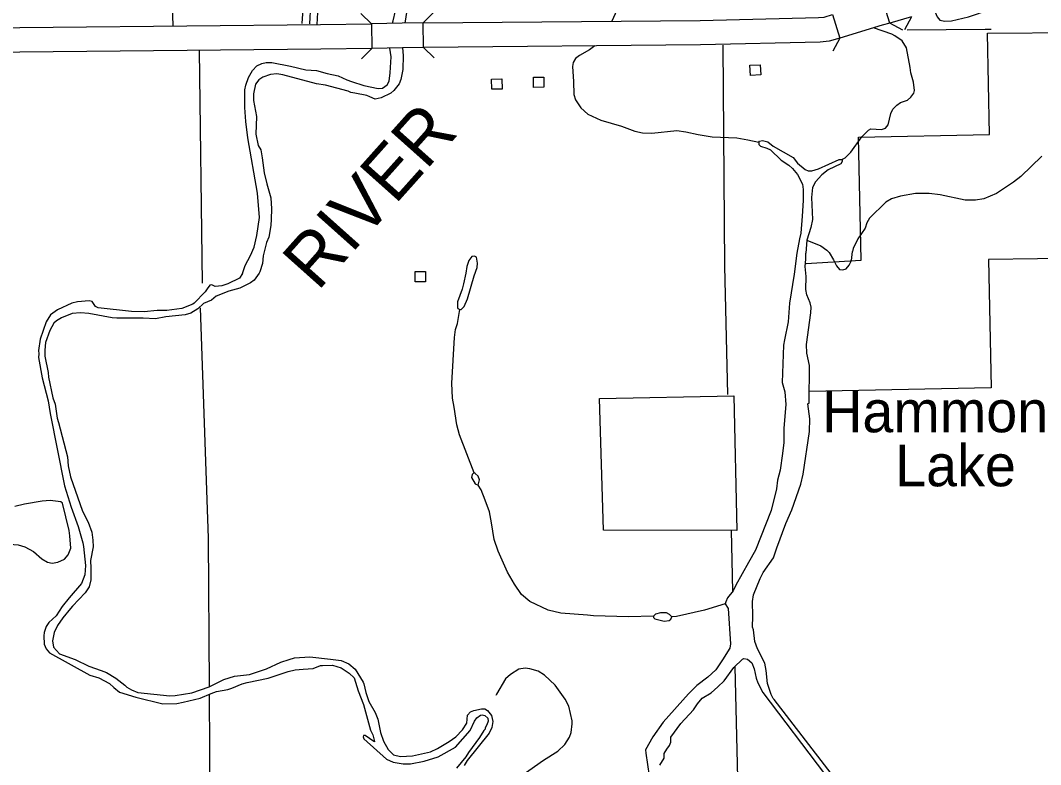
# Model space of a CAD drawing. Extents: x 1084508 to 1142749, y 1057638 to 1093403.
# Drawn here: x 1086974 to 1090220, y 1085312 to 1087680 of the extents above; entities that cross this region are included whole.
import ezdxf

# ---------------------------------------------------------------- set-up
doc = ezdxf.new("R2010")
doc.units = 0
for name, color, linetype in [('Level 10', 7, 'Continuous'), ('Level 32', 7, 'Continuous'), ('Level 35', 7, 'Continuous'), ('Level 37', 7, 'Continuous'), ('Level 4', 7, 'Continuous'), ('Level 5', 7, 'Continuous'), ('Level 56', 7, 'Continuous'), ('Level 7', 7, 'Continuous'), ('Level 9', 7, 'Continuous')]:
    doc.layers.add(name, color=color, linetype=linetype)

msp = doc.modelspace()

# ---------------------------------------------------------------- linework, layer by layer
at = {"layer": 'Level 10'}
for points in [[(1089740.3, 1087671.9), (1089717.5, 1087747)], [(1088255.8, 1087672.1), (1089137.3, 1087680.5), (1089513.8, 1087689.3), (1089532, 1087691.1), (1089558.6, 1087699.2)], [(1089558.6, 1087699.2), (1089581.5, 1087624.1)], [(1085801.9, 1087646.2), (1087928.8, 1087666.8), (1088091.3, 1087669.7)], [(1088255.8, 1087672.1), (1088189.3, 1087671.5), (1088091.3, 1087669.7)], [(1088091.3, 1087669.7), (1088092.5, 1087591.3)], [(1088257, 1087593.7), (1088255.8, 1087672.1)], [(1089740.3, 1087671.9), (1089716.4, 1087665.2), (1089581.5, 1087624.1)], [(1089809.9, 1087691.2), (1089740.3, 1087671.9)], [(1089581.5, 1087624.1), (1089547.4, 1087613.7), (1089518.5, 1087610.9), (1089138.6, 1087602.1), (1088257, 1087593.7)], [(1088092.5, 1087591.3), (1087929.9, 1087588.3), (1085800.4, 1087567.7)], [(1088257, 1087593.7), (1088190.4, 1087593), (1088092.5, 1087591.3)]]:
    msp.add_lwpolyline(points, dxfattribs=at)
at = {"layer": 'Level 32'}
for points in [[(1087886, 1087783.3), (1087874, 1087731.9), (1087870.2, 1087670.7)], [(1087908.9, 1087778), (1087897.4, 1087728.5), (1087893.7, 1087669.2)], [(1087931.9, 1087772.6), (1087920.8, 1087725), (1087917.2, 1087667.7)]]:
    msp.add_lwpolyline(points, dxfattribs=at)
at = {"layer": 'Level 35'}
for points in [[(1088858.8, 1087842.5), (1088838.1, 1087829.8), (1088818.6, 1087822.8), (1088794.4, 1087820.6), (1088699.8, 1087825.2), (1088627.7, 1087833.6), (1088569.4, 1087843.3), (1088529.9, 1087855.4), (1088502.3, 1087861.5), (1088475.4, 1087862.5), (1088454.7, 1087860.8), (1088410.3, 1087852.2), (1088343.8, 1087829.2), (1088293.6, 1087807.5), (1088265.3, 1087790.1), (1088244.4, 1087775.4), (1088229, 1087757.5), (1088210.3, 1087726.3), (1088203.6, 1087711.5), (1088197, 1087671.6)], [(1088858.8, 1087842.5), (1088876.8, 1087821.1), (1088886.7, 1087802.9), (1088909, 1087788), (1088916.4, 1087775.1), (1088916.8, 1087763.7), (1088909.1, 1087749.9), (1088872.1, 1087713.2), (1088855.6, 1087677.9)], [(1089883, 1087711.5), (1089891.2, 1087691.8), (1089899.5, 1087680.8), (1089915.6, 1087677.9), (1089936.3, 1087679.4), (1089990.7, 1087691.8), (1090056.2, 1087714.4)], [(1089762.7, 1087410.8), (1089774.1, 1087419.1), (1089796.8, 1087426.5), (1089807.5, 1087435.5), (1089817.1, 1087448.4), (1089819.3, 1087457.7), (1089815.8, 1087483.7), (1089807.7, 1087513.3), (1089805.7, 1087530.9), (1089793.1, 1087593.4), (1089779.3, 1087614.9), (1089756.4, 1087631.7), (1089747.4, 1087636.4), (1089688.8, 1087656.8)], [(1088802.4, 1087598.9), (1088784.8, 1087587.1), (1088752.7, 1087568.3), (1088739.9, 1087559), (1088732.8, 1087546.1), (1088731, 1087533.5), (1088733.7, 1087486.3), (1088735, 1087444.6), (1088740.1, 1087427.5), (1088757, 1087402.1)], [(1088190.4, 1087593.1), (1088192.6, 1087568.1), (1088191.1, 1087524.3), (1088184.9, 1087492.5)], [(1088184.9, 1087492.5), (1088178.9, 1087478.8), (1088162.7, 1087457.4), (1088152.9, 1087448.5), (1088122.3, 1087433.8), (1088102.5, 1087429.9), (1088085.6, 1087437.2), (1088076, 1087441.8), (1088038.6, 1087448.3), (1088026, 1087450.4), (1088017, 1087455.1), (1087944.5, 1087473.8), (1087916, 1087478.7), (1087809.4, 1087507.2), (1087789.8, 1087509.9), (1087770, 1087507.9), (1087745.1, 1087500), (1087732.9, 1087491.1), (1087722.4, 1087477.4), (1087716, 1087446.3), (1087715.8, 1087424.9), (1087725.5, 1087374.9), (1087722.9, 1087318.1), (1087731.2, 1087282.5), (1087738.9, 1087268.3), (1087743.9, 1087243.3)], [(1089352.1, 1087294), (1089369.2, 1087280.5), (1089432.8, 1087243.7), (1089447.2, 1087225.8), (1089471.5, 1087206.2), (1089480.3, 1087201.1), (1089492.2, 1087201), (1089514, 1087207.5), (1089579.1, 1087238), (1089587.5, 1087237.1), (1089598.6, 1087242.8), (1089616.2, 1087261.1), (1089651.5, 1087310), (1089672.5, 1087331.2), (1089680.2, 1087335.3), (1089714.3, 1087333.4), (1089727.2, 1087337.7), (1089735.2, 1087347.4), (1089743.2, 1087384), (1089749.7, 1087397.4), (1089762.7, 1087410.8)], [(1088757, 1087402.1), (1088779.2, 1087381.5), (1088820.8, 1087363), (1088886.7, 1087343.7), (1088929.2, 1087327.6), (1088953.3, 1087322.6), (1088982.9, 1087321.5), (1089062.4, 1087329.7), (1089091.1, 1087325.8), (1089131.1, 1087317.2), (1089174.8, 1087309.7)], [(1089174.8, 1087309.7), (1089254, 1087306.1), (1089288.3, 1087300)], [(1089288.3, 1087300), (1089323.8, 1087293), (1089326.2, 1087296.2), (1089335.2, 1087297.8), (1089352.1, 1087294)], [(1089323.8, 1087293), (1089323.7, 1087285.1), (1089328.9, 1087280.2), (1089349, 1087274.1), (1089361.2, 1087268.5)], [(1087743.9, 1087243.3), (1087750.1, 1087195), (1087758.1, 1087160), (1087770.7, 1087115.8), (1087773.6, 1087080.3), (1087772, 1087047.8), (1087771.5, 1087027.6), (1087764.7, 1086990.2), (1087757.7, 1086972.9), (1087747, 1086930.6), (1087744.1, 1086906.9), (1087735.7, 1086879.8), (1087733.6, 1086875.6)], [(1089361.3, 1087268.5), (1089394.5, 1087235.4), (1089419.1, 1087219.4), (1089430.4, 1087209.4), (1089446.3, 1087189.8), (1089462.3, 1087159.2), (1089464.7, 1087142.3), (1089464.8, 1087106.7), (1089461.6, 1087057.2), (1089457.3, 1087002.8), (1089453, 1086984.7), (1089444.6, 1086939)], [(1090223.8, 1087248.5), (1090157.5, 1087184), (1090133.6, 1087165.8), (1090080.2, 1087129.8), (1090039.9, 1087112.2), (1090013, 1087107.7), (1089980.2, 1087108.4), (1089900.2, 1087124.9), (1089865.4, 1087129.6), (1089822.6, 1087129.6), (1089774.7, 1087120.8), (1089746.1, 1087112.8), (1089728.2, 1087102.1), (1089676.3, 1087051), (1089667.7, 1087035.9), (1089662, 1087019), (1089639, 1086985.4), (1089624.1, 1086953.9), (1089621.9, 1086945)], [(1089588.4, 1087236.7), (1089589, 1087231.4), (1089584.5, 1087223.3), (1089544.3, 1087204.5), (1089524.1, 1087189), (1089503.5, 1087166.8), (1089494.4, 1087148.2), (1089491.5, 1087116.9), (1089494.4, 1087046.1), (1089489, 1087021.6), (1089476.4, 1086980.9), (1089520.5, 1086962.7), (1089540.2, 1086949.5), (1089547.4, 1086941.6)], [(1089476.4, 1086980.9), (1089472.9, 1086939.5)], [(1088417.5, 1086240.1), (1088371.2, 1086360.8), (1088362.5, 1086393.5), (1088354, 1086449.6), (1088348.9, 1086478.1), (1088346.7, 1086526), (1088355, 1086671.2), (1088358.2, 1086696.9), (1088364.6, 1086716.1), (1088372, 1086760.6), (1088376.5, 1086759.9), (1088386.1, 1086769.8), (1088396.3, 1086794.3), (1088417.8, 1086867.8), (1088427.1, 1086893.5), (1088428.9, 1086907.5), (1088425.2, 1086926.6), (1088419.1, 1086930.1), (1088411, 1086928.7), (1088400.6, 1086916), (1088394.8, 1086897.4), (1088391, 1086875.8), (1088384.4, 1086841.4), (1088380.1, 1086824.8), (1088365, 1086784.6), (1088365.1, 1086766.3), (1088366.2, 1086763.2), (1088369.8, 1086761.2)], [(1089444.6, 1086939), (1089436.1, 1086872.6), (1089421.7, 1086780.1), (1089417.5, 1086720.9), (1089405.9, 1086663.5), (1089402.2, 1086646.6), (1089398.2, 1086527.8), (1089406.1, 1086498.2), (1089409.5, 1086457.3), (1089402.8, 1086382.5), (1089403, 1086337.1), (1089398.9, 1086302.2), (1089391.2, 1086249.2), (1089383.6, 1086217.2), (1089379.8, 1086189.3), (1089362.5, 1086120), (1089312.8, 1085993.7), (1089291, 1085954.9), (1089250.5, 1085882.3), (1089242.2, 1085864.9), (1089224.3, 1085842.6), (1089218.6, 1085830)], [(1089475.5, 1086649.1), (1089489.1, 1086750), (1089490.2, 1086767.4), (1089487.1, 1086781.5), (1089476.5, 1086806.9), (1089473.5, 1086824.1), (1089474.5, 1086865.2), (1089471.5, 1086897.5), (1089473.6, 1086920.7), (1089472.9, 1086939.5)], [(1089547.4, 1086941.6), (1089561.8, 1086918.4), (1089570.8, 1086899.6), (1089580.1, 1086888), (1089590.6, 1086886), (1089601.1, 1086889.9), (1089611.3, 1086900.8), (1089618.2, 1086916), (1089621.9, 1086945)], [(1089372.9, 1085519), (1089369.6, 1085522), (1089363.4, 1085535.3), (1089350.8, 1085569.8), (1089347, 1085611.6), (1089342.8, 1085635), (1089319.4, 1085679.7), (1089310.5, 1085703.3), (1089306.3, 1085740.3), (1089304, 1085749.4), (1089304.6, 1085784.4), (1089303.8, 1085831.1), (1089307.2, 1085852.4), (1089327.5, 1085904.2), (1089337.1, 1085922.6), (1089370.5, 1085970.2), (1089380.7, 1086001.6), (1089409.9, 1086079.3), (1089428.4, 1086122.7), (1089457.2, 1086203.9), (1089464.5, 1086235.8), (1089484.5, 1086372.1), (1089485.8, 1086412.2), (1089479.6, 1086459.6), (1089483.5, 1086462.9), (1089484.8, 1086581.6), (1089476.4, 1086621), (1089475.5, 1086649.1)], [(1088416.9, 1086240.1), (1088411.8, 1086234.5), (1088409.7, 1086225.6), (1088420.7, 1086205.6), (1088430.3, 1086201.3)], [(1089216.3, 1085823.3), (1089151.2, 1085803), (1089061.8, 1085783.4), (1089046.7, 1085781.8), (1089039.2, 1085789.6), (1089029.5, 1085794.5), (1089010.6, 1085794.9), (1088995.4, 1085790.5), (1088988.1, 1085784.4), (1088908.9, 1085782.1), (1088797.7, 1085785.2), (1088778.7, 1085787.8), (1088693.8, 1085794), (1088653.1, 1085802.8), (1088595.6, 1085830.5), (1088569.1, 1085852.6), (1088546.2, 1085885.7), (1088523.7, 1085924.1), (1088493.9, 1085990.6), (1088481.5, 1086028.5), (1088473.2, 1086081.4), (1088466.6, 1086115.9), (1088453.2, 1086153.7), (1088440.4, 1086186.3), (1088430.3, 1086201.3), (1088435.2, 1086217.6), (1088431.2, 1086230), (1088420.8, 1086238.4), (1088417.5, 1086240.1)], [(1087131.6, 1086039.5), (1087128.9, 1086056.7), (1087108, 1086144.1), (1087102.7, 1086148), (1087068.6, 1086151.8), (1087043.8, 1086150.6), (1086987.6, 1086140.2), (1086956.8, 1086133.4)], [(1086512.6, 1085950.2), (1086540.2, 1085917.7), (1086543.8, 1085915.3), (1086552.5, 1085917.6), (1086641.6, 1085951), (1086653.7, 1085953.8), (1086758.3, 1085986.7), (1086810.8, 1086001.7), (1086864.9, 1086014.3), (1086894.1, 1086016), (1086911.7, 1086015.8), (1086967.6, 1086011.1), (1086988.4, 1086005.1), (1087015.8, 1085990), (1087042.7, 1085966.3), (1087060.1, 1085955.7), (1087075.7, 1085952.6), (1087093.8, 1085956.3), (1087114.4, 1085965.5), (1087126.1, 1085978.9), (1087134.9, 1086000.2), (1087131.6, 1086039.5)], [(1089218.6, 1085830), (1089216.3, 1085823.3), (1089226.1, 1085808.9), (1089233.8, 1085695.7), (1089231.2, 1085682.6), (1089208, 1085645), (1089187.4, 1085613.4), (1089161.1, 1085589.8), (1089126.4, 1085563.9), (1089100.3, 1085536.8), (1089019.4, 1085446.6), (1088986, 1085399.7), (1088963.3, 1085358.5), (1088963.8, 1085348.2), (1088975.2, 1085275.5)], [(1088988.1, 1085784.4), (1088988.6, 1085779.7), (1088992.6, 1085776.1), (1089022.2, 1085768.3), (1089038.5, 1085770.3), (1089043.6, 1085774.4), (1089046.7, 1085781.8)], [(1089039.1, 1085372.8), (1089043.7, 1085383.4), (1089044.2, 1085398.6), (1089075.6, 1085442.6), (1089115.5, 1085485.8), (1089128.4, 1085505.3), (1089143.4, 1085522.7), (1089171.9, 1085540.1), (1089193.4, 1085558.8), (1089213.3, 1085578.3), (1089244.1, 1085620.4), (1089272.1, 1085646.9), (1089276.4, 1085649), (1089287.8, 1085647.4), (1089301.9, 1085635.1), (1089309.1, 1085616.8), (1089314.8, 1085586.7), (1089320.5, 1085571.9), (1089336.7, 1085540.7), (1089533.1, 1085282.1), (1089568.2, 1085230.9)], [(1088516.2, 1085239.6), (1088639.1, 1085326), (1088684.7, 1085354.9), (1088706.4, 1085375.8), (1088721.4, 1085398.6), (1088726.4, 1085413.3), (1088729.6, 1085440.9), (1088729.7, 1085451), (1088718.8, 1085497.9), (1088707.1, 1085520), (1088675.2, 1085564.3), (1088642, 1085596), (1088621.6, 1085609.2), (1088595.4, 1085616.9), (1088580.6, 1085618.1), (1088560.6, 1085615.3), (1088533.3, 1085598.9), (1088517.3, 1085584.2), (1088489.3, 1085536.2), (1088487, 1085531.1)], [(1089582.2, 1085245.9), (1089372.9, 1085519)], [(1089008.3, 1085310.1), (1089022.1, 1085331.9), (1089022.7, 1085346.8), (1089030.5, 1085360.7), (1089039.1, 1085372.8)]]:
    msp.add_lwpolyline(points, dxfattribs=at)
at = {"layer": 'Level 37'}
for points in [[(1088057.5, 1087702.5), (1088091.3, 1087669.7)], [(1088255.8, 1087672.1), (1088288.5, 1087705.9)], [(1089781.9, 1087649.7), (1089740.3, 1087671.9)], [(1089809.9, 1087691.2), (1089786.7, 1087650.2)], [(1089581.5, 1087624.1), (1089559.3, 1087582.6)], [(1088092.5, 1087591.3), (1088059.8, 1087557.5)], [(1088290.8, 1087560.9), (1088257, 1087593.7)]]:
    msp.add_lwpolyline(points, dxfattribs=at)
at = {"layer": 'Level 4'}
msp.add_lwpolyline([(1090063.3, 1087651.6), (1090043.8, 1087651.3), (1089795.6, 1087649.1)], dxfattribs=at)
at = {"layer": 'Level 5'}
msp.add_line((1087543.3, 1087584.6), (1087552.4, 1086843.6), dxfattribs=at)
for points in [[(1087372.3, 1090942.1), (1087391.7, 1090120.4), (1087410.2, 1089282), (1087459.1, 1087662.2)], [(1089209.3, 1087601.3), (1089214.1, 1086898.4), (1089223.9, 1086489.4)], [(1087545.9, 1086765.7), (1087571.4, 1086031.9), (1087574.3, 1085558.7)], [(1089235.9, 1086056.4), (1089239.4, 1085913), (1089240.4, 1085861.2)], [(1089247.1, 1085623.3), (1089256.6, 1085224.9), (1089261.8, 1084966.8)], [(1087574.5, 1085535.1), (1087576.6, 1085186.7), (1087591.7, 1084372)]]:
    msp.add_lwpolyline(points, dxfattribs=at)
at = {"layer": 'Level 56'}
for points in [[(1089296.8, 1087505.4), (1089295.6, 1087538), (1089328.4, 1087539.3), (1089329.6, 1087506.6)], [(1088474.1, 1087461), (1088473.6, 1087493.7), (1088506.4, 1087494.1), (1088506.8, 1087461.5)], [(1088607.3, 1087466.6), (1088606.6, 1087499.2), (1088639.3, 1087499.9), (1088640, 1087467.3)], [(1088230.1, 1086848.2), (1088230.1, 1086880.9), (1088262.8, 1086880.9), (1088262.8, 1086848.2)]]:
    msp.add_lwpolyline(points, close=True, dxfattribs=at)
at = {"layer": 'Level 7'}
for points in [[(1089473, 1086904.1), (1089473, 1086906.3), (1089649, 1086917), (1089641.2, 1087308.4), (1090057.9, 1087316.8), (1090051.4, 1087640.2), (1090337.1, 1087641.8)], [(1090867.8, 1087146.3), (1090674.1, 1087142.4), (1090678.3, 1086928.3), (1090054.3, 1086919.8), (1090062.5, 1086510.4), (1089483.9, 1086498.9)]]:
    msp.add_lwpolyline(points, dxfattribs=at)
msp.add_lwpolyline([(1089244, 1086485.9), (1089253.7, 1086056.7), (1088829.8, 1086057.3), (1088816.3, 1086477)], close=True, dxfattribs=at)
at = {"layer": 'Level 9'}
for points in [[(1088158.5, 1087671), (1088159.8, 1087679), (1088168.1, 1087710.8), (1088198.1, 1087766.8), (1088220.4, 1087794.7), (1088257, 1087826.6), (1088282.8, 1087843.6), (1088312.5, 1087858), (1088334.3, 1087863.8), (1088370.7, 1087884.7), (1088386.2, 1087892.6), (1088522.9, 1087901.8), (1088545.9, 1087898.8), (1088572.7, 1087889.8), (1088624.8, 1087877.2)], [(1088027.2, 1087485.4), (1088067.3, 1087473.3), (1088112.4, 1087463.4), (1088125.9, 1087465.1), (1088141.3, 1087474.9), (1088147.1, 1087487), (1088151.2, 1087513), (1088153.7, 1087564.1), (1088149.9, 1087592.3)], [(1087680.8, 1086874.9), (1087689.9, 1086900.4), (1087706.4, 1086931.6), (1087717.7, 1086958.2), (1087726.7, 1086995.4), (1087734.6, 1087052.7), (1087728.9, 1087129.9), (1087697.5, 1087306.4), (1087691.2, 1087358.5), (1087688.3, 1087403.1), (1087688.1, 1087459.8), (1087691.3, 1087474.4), (1087700.2, 1087498.7), (1087712.5, 1087521.2), (1087726.8, 1087535.6), (1087742.4, 1087543.6), (1087756, 1087546.7), (1087774, 1087546.1), (1087833.3, 1087535.1), (1087882.5, 1087523.1), (1087916.3, 1087520.9), (1087950, 1087510.8), (1087985.6, 1087504), (1088012.5, 1087490.8), (1088027.2, 1087485.4)], [(1087680.8, 1086874.9), (1087671.2, 1086860.1), (1087634, 1086841.7), (1087615.4, 1086835.1), (1087594.4, 1086833.2), (1087582.8, 1086838.7), (1087576.9, 1086837.5), (1087568, 1086826), (1087561.8, 1086816.3), (1087526.6, 1086780.6), (1087522.7, 1086777.5), (1087487.5, 1086763), (1087440.2, 1086756.7), (1087409.4, 1086757.2), (1087367.7, 1086753.1), (1087327.7, 1086754.1), (1087221.2, 1086765), (1087212.8, 1086769.6), (1087203, 1086785.3), (1087193.1, 1086787.7), (1087156.1, 1086785), (1087137.7, 1086780.7), (1087092.4, 1086759.4), (1087069.9, 1086742.9), (1087056.1, 1086721.4), (1087036.9, 1086665.3), (1087032.2, 1086630.1), (1087032.4, 1086618.7)], [(1087733.6, 1086875.6), (1087718.1, 1086853.1), (1087706.5, 1086844.7), (1087672.7, 1086828), (1087637.6, 1086818.2), (1087597.1, 1086802.4), (1087582.5, 1086789.8), (1087556.6, 1086779.7), (1087538.5, 1086762.2), (1087516.8, 1086748.2), (1087498.4, 1086743.6), (1087437, 1086736.7), (1087404.3, 1086730.1), (1087364.8, 1086733.1), (1087280.8, 1086733), (1087266, 1086733.6), (1087191.8, 1086747.2), (1087165.9, 1086749.2), (1087138.9, 1086747.3), (1087104.6, 1086733.7), (1087088.7, 1086723.6), (1087081.1, 1086716.9), (1087068.1, 1086692.9), (1087054.4, 1086655.1), (1087051.7, 1086630.7), (1087051.9, 1086611.4), (1087062.5, 1086559.5), (1087063.7, 1086544.7), (1087077.4, 1086478.8), (1087084.9, 1086458.6), (1087091.7, 1086413.8), (1087095.4, 1086401)], [(1087032.4, 1086618.7), (1087031.4, 1086607), (1087043.7, 1086542.2), (1087062.1, 1086469.9), (1087069, 1086429.5), (1087114.9, 1086198.4), (1087135.3, 1086130.8), (1087157.9, 1086069.7), (1087173.1, 1086017.4), (1087174.9, 1086005.8), (1087181.4, 1085945.2), (1087179.3, 1085916.1), (1087168.3, 1085888.4), (1087129.1, 1085842.4), (1087107.4, 1085814.6), (1087088, 1085785), (1087065, 1085764.4), (1087055.9, 1085750.7), (1087049.5, 1085732.1), (1087048.4, 1085721.3), (1087049.9, 1085695.2), (1087056.2, 1085680), (1087067.2, 1085667.9), (1087194.7, 1085596.5), (1087223.3, 1085588.3), (1087258.2, 1085569.4), (1087271, 1085557.4)], [(1087095.4, 1086401), (1087124.3, 1086291), (1087126.5, 1086262.7), (1087133.4, 1086227.9), (1087172.1, 1086118), (1087189.6, 1086083.8), (1087201.5, 1086051.5), (1087204.8, 1086026.4), (1087205.5, 1086004.4), (1087197.7, 1085960.8), (1087198.2, 1085936.5), (1087198.6, 1085899.3), (1087192.7, 1085877.5), (1087180, 1085858.3), (1087140.1, 1085816.4), (1087134.1, 1085808.3), (1087109.7, 1085778.7), (1087091.9, 1085754.3), (1087081.5, 1085732.6), (1087076.5, 1085705.3), (1087079.9, 1085685.5), (1087098.8, 1085664.3), (1087148.3, 1085646.7), (1087192.1, 1085625.1), (1087231.1, 1085611.4)], [(1087231.1, 1085611.4), (1087248.4, 1085604.3), (1087277.5, 1085586.7), (1087306.8, 1085564.7), (1087312.8, 1085558.6), (1087327.4, 1085549.5), (1087347.6, 1085541), (1087449.3, 1085530.8), (1087466.9, 1085531.6), (1087520, 1085540.4), (1087575.2, 1085559), (1087621.3, 1085582.3), (1087655.8, 1085592.7), (1087703, 1085598.6), (1087757.6, 1085616), (1087802.6, 1085637.3), (1087829.2, 1085646.7), (1087846, 1085651.9), (1087895.5, 1085655.1), (1087960.7, 1085647.7), (1087994.3, 1085642.6), (1088019.3, 1085632.7), (1088039.2, 1085615.6), (1088065, 1085574.5)], [(1087271, 1085557.4), (1087289.6, 1085541.8), (1087341.6, 1085525.9), (1087427.8, 1085505.2), (1087471.8, 1085506.6), (1087491.8, 1085510.1), (1087546, 1085523), (1087581.5, 1085538.2), (1087597.9, 1085544.6), (1087634.4, 1085551), (1087646.8, 1085555), (1087679.5, 1085568.8), (1087695.4, 1085573), (1087762.4, 1085587.2), (1087826.2, 1085608.1), (1087848, 1085613.2), (1087873.4, 1085615.6), (1087906.1, 1085617.4), (1087929.5, 1085626.7), (1087935.8, 1085627.3), (1087966.9, 1085628.1), (1087994.7, 1085619.6), (1088020.3, 1085602.5), (1088035.8, 1085588)], [(1088035.8, 1085588), (1088048.9, 1085546.7), (1088065.4, 1085502.6), (1088088.6, 1085421.6), (1088095.9, 1085406.2), (1088100.1, 1085389.6), (1088100.6, 1085384.6), (1088098.4, 1085385.1), (1088071.1, 1085404.1), (1088065.8, 1085404.2), (1088064.4, 1085399.7), (1088066.9, 1085393.8), (1088138.7, 1085328.9), (1088159.9, 1085319.2), (1088191.6, 1085314.3), (1088215.5, 1085314.5), (1088258.9, 1085322.1), (1088303.6, 1085335.9), (1088359.1, 1085367.4), (1088405.2, 1085420.4), (1088418.6, 1085449.4), (1088426.3, 1085460.1), (1088438.2, 1085469.5), (1088443.8, 1085470.4), (1088452.4, 1085468.3), (1088461.9, 1085459.9), (1088462.3, 1085450.4)], [(1088065, 1085574.5), (1088067.1, 1085568.9), (1088073.7, 1085541.5), (1088082.6, 1085512.2), (1088103, 1085477.5), (1088111.5, 1085456.7), (1088119.8, 1085413.6), (1088129.2, 1085385.9), (1088144.6, 1085359.2), (1088161.4, 1085342.3), (1088183.3, 1085337.9), (1088221.3, 1085340), (1088278.6, 1085352.7), (1088301.4, 1085362.6), (1088338.5, 1085385.1), (1088359.5, 1085400.3), (1088380.8, 1085422.4), (1088394.3, 1085443.8), (1088397.3, 1085469.5), (1088406.6, 1085480.1), (1088417.4, 1085483.7), (1088441, 1085489.5), (1088451.8, 1085489.1), (1088460.8, 1085483.8), (1088473.2, 1085468), (1088477.5, 1085449.2), (1088474.2, 1085430.2), (1088465.3, 1085412.1), (1088395.6, 1085324.6), (1088386.6, 1085308.7)], [(1088462.3, 1085450.4), (1088458.5, 1085438.3), (1088453.5, 1085428.9), (1088453.4, 1085424.5), (1088448.6, 1085420.1), (1088434.5, 1085397.7), (1088400.2, 1085349.8), (1088391.9, 1085336.8), (1088361.5, 1085300.6)]]:
    msp.add_lwpolyline(points, dxfattribs=at)

# ---------------------------------------------------------------- texts
at = {"layer": 'Level 35'}
for s, p in [('Hammond', (1089525.2, 1086369.4)), ('Lake', (1089757.4, 1086197.5))]:
    msp.add_text(s, height=132.58, dxfattribs=at).set_placement(p)
at = {"layer": 'Level 9'}
msp.add_text('RIVER', height=165.73, rotation=48.2379, dxfattribs=at).set_placement((1087920.1, 1086815.9))

doc.saveas('drawing.dxf')
